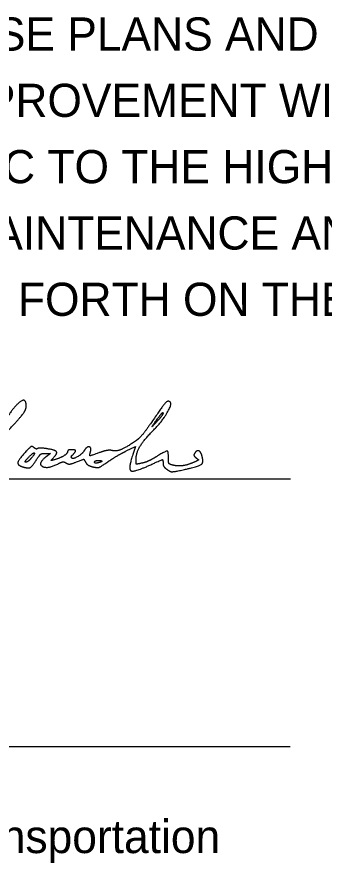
# Model space of a CAD drawing. Extents: x 0 to 34, y 0 to 22.
# Drawn here: x 26.875 to 28.171, y 7.305 to 10.877 of the extents above; entities that cross this region are included whole.
import ezdxf

# ---------------------------------------------------------------- set-up
doc = ezdxf.new("R2010")
doc.units = 0
for name, color, linetype in [('Default', 7, 'Continuous'), ('SH_Data', 7, 'Continuous'), ('SH_Text', 7, 'Continuous')]:
    doc.layers.add(name, color=color, linetype=linetype)

msp = doc.modelspace()

# ---------------------------------------------------------------- linework, layer by layer
at = {"layer": 'SH_Data'}
for p, q in [((24.5279, 8.9262), (28.0279, 8.9262)), ((24.5289, 8.9265), (28.0289, 8.9265)), ((24.5279, 7.7968), (28.0279, 7.7968)), ((24.5279, 7.7968), (28.0279, 7.7968))]:
    msp.add_line(p, q, dxfattribs=at)
at = {"layer": 'SH_Text'}
for points in [[(27.3364, 9.0447), (27.3751, 9.064), (27.3637, 9.0293)], [(26.9957, 9.0344), (27.0165, 9.0342), (26.9982, 9.0202)]]:
    msp.add_lwpolyline(points, dxfattribs=at)
for points in [[(26.9139, 9.2335), (26.9139, 9.2748), (26.8522, 9.2218), (26.8013, 9.1366)], [(27.5202, 9.2522), (27.5105, 9.2582), (27.4906, 9.2355), (27.438, 9.1587)], [(26.8218, 9.1144), (26.8811, 9.1764), (26.9139, 9.2188), (26.9139, 9.2335)], [(27.4492, 9.1304), (27.488, 9.1697), (27.5319, 9.245), (27.5202, 9.2522)], [(27.4679, 9.1711), (27.4433, 9.1438), (27.4464, 9.1516), (27.475, 9.1895)], [(27.4915, 9.2044), (27.4915, 9.2005), (27.4809, 9.1856), (27.4679, 9.1711)], [(27.475, 9.1895), (27.4841, 9.2016), (27.4915, 9.2083), (27.4915, 9.2044)], [(27.438, 9.1587), (27.4175, 9.1288), (27.3913, 9.0976), (27.3796, 9.0894)], [(27.3775, 9.0086), (27.3775, 9.0356), (27.41, 9.0908), (27.4492, 9.1304)], [(27.3796, 9.0894), (27.3388, 9.0607), (27.2941, 9.0418), (27.2768, 9.0462)], [(26.9098, 9.0386), (26.8802, 9.0062), (26.8763, 8.9847), (26.8987, 8.9776)], [(26.9466, 9.0586), (26.9383, 9.0655), (26.9306, 9.0613), (26.9098, 9.0386)], [(26.9618, 9.0546), (26.9592, 9.052), (26.9524, 9.0538), (26.9466, 9.0586)], [(27.001, 9.054), (26.982, 9.0569), (26.9643, 9.0571), (26.9618, 9.0546)], [(27.026, 9.0124), (27.0462, 9.0336), (27.0372, 9.0486), (27.001, 9.054)], [(27.0887, 9.043), (27.0887, 9.0344), (27.06, 9.0156), (27.0355, 9.0082)], [(27.1039, 9.0498), (27.0956, 9.0498), (27.0887, 9.0467), (27.0887, 9.043)], [(27.1101, 9.0286), (27.1234, 9.0419), (27.1211, 9.0498), (27.1039, 9.0498)], [(27.1594, 9.0472), (27.1506, 9.0324), (27.1119, 9.0088), (27.1061, 9.0147)], [(27.1853, 9.0422), (27.1899, 9.0598), (27.1693, 9.0638), (27.1594, 9.0472)], [(27.2265, 9.0387), (27.1837, 9.0236), (27.1805, 9.0239), (27.1853, 9.0422)], [(27.2768, 9.0462), (27.2674, 9.0485), (27.2448, 9.0452), (27.2265, 9.0387)], [(27.2585, 8.9988), (27.2801, 9.0135), (27.3151, 9.0341), (27.3364, 9.0447)], [(27.5143, 9.0115), (27.5143, 9.0436), (27.5045, 9.0453), (27.4634, 9.0204)], [(27.6546, 9.028), (27.6496, 9.0438), (27.6321, 9.0469), (27.6238, 9.0334)], [(26.8987, 8.9776), (26.922, 8.9702), (26.9389, 8.9789), (26.9577, 9.008)], [(26.9114, 8.9966), (26.9072, 8.9966), (26.9117, 9.0051), (26.9215, 9.0155)], [(26.933, 9.0118), (26.9254, 9.0034), (26.9157, 8.9966), (26.9114, 8.9966)], [(26.9215, 9.0155), (26.9424, 9.0378), (26.9533, 9.0343), (26.933, 9.0118)], [(26.9577, 9.008), (26.9705, 9.0278), (26.9801, 9.0345), (26.9957, 9.0344)], [(26.9982, 9.0202), (26.9605, 8.9912), (27.0042, 8.9673), (27.0507, 8.9915)], [(27.0355, 9.0082), (27.02, 9.0035), (27.0183, 9.0043), (27.026, 9.0124)], [(27.1061, 9.0147), (27.1034, 9.0174), (27.1052, 9.0237), (27.1101, 9.0286)], [(27.1261, 8.9984), (27.1555, 9.0099), (27.1576, 9.0098), (27.1647, 8.9966)], [(27.2027, 8.9973), (27.2027, 9.0011), (27.2096, 9.0042), (27.2179, 9.0042)], [(27.2179, 9.0042), (27.2263, 9.0042), (27.2331, 9.0029), (27.2331, 9.0013)], [(27.3637, 9.0293), (27.3437, 8.9685), (27.3676, 8.9536), (27.4354, 8.9846)], [(27.4022, 8.993), (27.3791, 8.9881), (27.3775, 8.9891), (27.3775, 9.0086)], [(27.4634, 9.0204), (27.4434, 9.0082), (27.4158, 8.9958), (27.4022, 8.993)], [(27.4354, 8.9846), (27.4856, 9.0076), (27.4915, 9.0083), (27.4915, 8.9917)], [(27.5334, 8.9845), (27.5185, 8.9882), (27.5143, 8.9941), (27.5143, 9.0115)], [(27.5827, 8.9665), (27.6442, 8.9801), (27.6643, 8.9973), (27.6546, 9.028)], [(27.6238, 9.0334), (27.6208, 9.0286), (27.624, 9.0206), (27.6308, 9.0156)], [(27.6308, 9.0156), (27.642, 9.0074), (27.6414, 9.0056), (27.6251, 8.9982)], [(27.0507, 8.9915), (27.0639, 8.9983), (27.0736, 8.999), (27.0824, 8.9937)], [(27.0824, 8.9937), (27.0913, 8.9884), (27.1041, 8.9897), (27.1261, 8.9984)], [(27.1647, 8.9966), (27.1688, 8.9889), (27.1828, 8.9803), (27.1958, 8.9774)], [(27.1958, 8.9774), (27.2151, 8.9732), (27.2264, 8.977), (27.2585, 8.9988)], [(27.2179, 8.9944), (27.2096, 8.9922), (27.2027, 8.9935), (27.2027, 8.9973)], [(27.2331, 9.0013), (27.2331, 8.9997), (27.2263, 8.9966), (27.2179, 8.9944)], [(27.4915, 8.9917), (27.4915, 8.9849), (27.4975, 8.9747), (27.5048, 8.9691)], [(27.5048, 8.9691), (27.5208, 8.957), (27.5373, 8.9565), (27.5827, 8.9665)], [(27.6251, 8.9982), (27.5973, 8.9855), (27.5546, 8.9792), (27.5334, 8.9845)]]:
    msp.add_open_spline(points, degree=2, dxfattribs=at)

# ---------------------------------------------------------------- texts
at = {"layer": 'Default'}
for s, p in [('I HEREBY APPROVE THESE PLANS AND DECLARE THAT', (24.5279, 10.735)), ('THE MAKING OF THIS IMPROVEMENT WILL NOT REQUIRE', (24.5279, 10.455)), ('THE CLOSING TO TRAFFIC TO THE HIGHWAY AND THAT', (24.5279, 10.175)), ('PROVISIONS FOR THE MAINTENANCE AND SAFETY OF ', (24.5279, 9.895)), ('TRAFFIC WILL BE AS SET FORTH ON THE PLANS AND', (24.5279, 9.615))]:
    msp.add_text(s, height=0.14, dxfattribs=at).set_placement(p)
at = {"layer": 'SH_Text'}
msp.add_text('Director, Department of Transportation', height=0.14, dxfattribs=at).set_placement((24.5279, 7.3468))

doc.saveas('drawing.dxf')
